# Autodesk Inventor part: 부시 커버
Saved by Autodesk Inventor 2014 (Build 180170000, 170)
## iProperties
Created: 2024-08
Part Number: 부시 커버
Material: 일반
Document SubType Name: Modeling
Designer: dg
Density: 1 g/cm^3
Appearance: 기본값
Author: dg
Author: jhkim
Creation Date: 2024-08-09
Sending System: Autodesk Inventor 2025
Preprocessor: ST-DEVELOPER v20
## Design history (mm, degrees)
node "부시 커버1"
node "솔리드1"
node "기준1"
